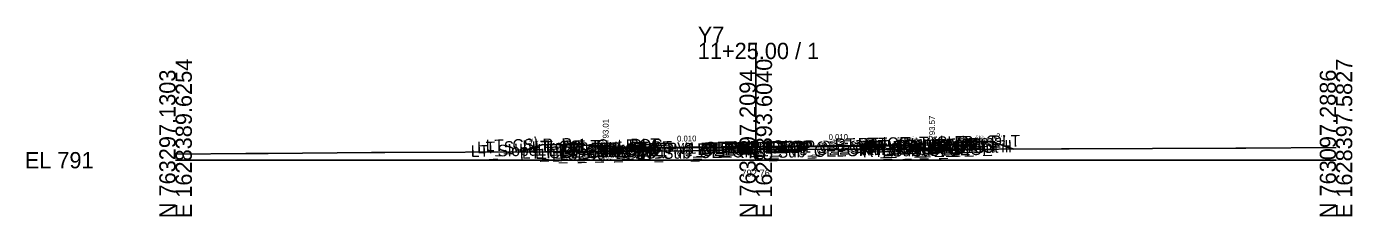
# Model space of a CAD drawing. Extents: x -26 to 203, y -10 to 3017.
# Drawn here: x -25.7 to 202.8, y 2490.3 to 2523 of the extents above; entities that cross this region are included whole.
import ezdxf

# ---------------------------------------------------------------- set-up
doc = ezdxf.new("R2010")
doc.units = 0
for name, color, linetype in [('Default', 7, 'Continuous'), ('Exist Cross Section Cell', 7, 'Continuous'), ('Exist XS Center Line Elevation Label', 7, 'Continuous'), ('Exist XS Ground Line', 7, 'Continuous'), ('Prop CMT Conc Surface', 7, 'Continuous'), ('Prop CMT Concrete Structures', 7, 'Continuous'), ('Prop CMT Pvmt Course 1', 7, 'Continuous'), ('Prop CMT Pvmt Course 1 CG', 7, 'Continuous'), ('Prop CMT Pvmt Course 2', 7, 'Continuous'), ('Prop CMT Pvmt Course 3', 7, 'Continuous'), ('Prop CMT Pvmt Surface', 7, 'Continuous'), ('Prop CMT Slope Grass', 7, 'Continuous'), ('Prop CMT Subgrade Earthwork', 7, 'Continuous'), ('Prop XS Hydro Elevations', 7, 'Continuous'), ('Prop XS SE Text', 7, 'Continuous'), ('Prop XS Side Slope Text', 7, 'Continuous'), ('Scratch_Level_0', 7, 'Continuous')]:
    doc.layers.add(name, color=color, linetype=linetype)

msp = doc.modelspace()

# ---------------------------------------------------------------- linework, layer by layer
at = {"layer": 'Exist Cross Section Cell'}
for p, q in [((100, 2500), (100, 2520.22)), ((0, 2500), (100, 2500)), ((100, 2500), (200, 2500))]:
    msp.add_line(p, q, dxfattribs=at)
at = {"layer": 'Exist XS Ground Line'}
msp.add_lwpolyline([(0, 2501.03), (12.12, 2501.13), (14.45, 2501.15), (15.97, 2501.16), (33.79, 2501.3), (36.07, 2501.31), (63.79, 2501.44), (64.5, 2501.44), (71.82, 2501.47), (76.09, 2501.54), (77.94, 2501.51), (81.73, 2501.57), (88.9, 2501.61), (94.12, 2501.71), (100, 2501.76), (116.44, 2501.9), (118.29, 2501.87), (119.92, 2501.85), (122.36, 2501.84), (126.12, 2501.84), (127.58, 2501.85), (131.01, 2501.84), (152.68, 2501.93), (154, 2501.94), (182.73, 2502.05), (183.61, 2502.06), (184.48, 2502.06), (200, 2502.19)], dxfattribs=at)
at = {"layer": 'Prop CMT Conc Surface'}
for points in [[(74.13, 2502.01), (74.13, 2502.51), (73.63, 2502.51)], [(128.38, 2502.63), (130.38, 2502.57)], [(130.38, 2502.57), (130.38, 2503.07), (130.88, 2503.07)], [(76.13, 2502.11), (74.13, 2502.01)]]:
    msp.add_lwpolyline(points, dxfattribs=at)
at = {"layer": 'Prop CMT Concrete Structures'}
for points in [[(76.13, 2502.11), (74.13, 2502.01), (74.13, 2502.51), (73.63, 2502.51)], [(73.63, 2502.51), (73.63, 2501.5), (76.13, 2501.52)], [(128.38, 2502.63), (130.38, 2502.57), (130.38, 2503.07), (130.88, 2503.07)], [(130.88, 2503.07), (130.88, 2502.07), (128.38, 2502.05)], [(128.38, 2502.05), (128.38, 2502.63)], [(76.13, 2501.52), (76.13, 2502.11)]]:
    msp.add_lwpolyline(points, dxfattribs=at)
at = {"layer": 'Prop CMT Pvmt Course 1'}
for points in [[(100, 2502.35), (128.38, 2502.63)], [(127.38, 2502.5), (100, 2502.22)], [(127.38, 2502.37), (127.38, 2502.5)], [(128.38, 2502.63), (128.38, 2502.38)], [(100, 2502.35), (76.13, 2502.11)], [(76.13, 2502.11), (76.13, 2501.86)], [(76.13, 2501.86), (77.13, 2501.87)], [(77.13, 2501.99), (100, 2502.22)], [(77.13, 2501.87), (77.13, 2501.99)], [(100, 2502.1), (100, 2502.35)], [(100, 2502.1), (100, 2502.35)], [(100, 2502.22), (100, 2502.1), (100, 2502.1)], [(100, 2502.22), (100, 2502.1), (100, 2502.1)], [(128.38, 2502.38), (127.38, 2502.37)]]:
    msp.add_lwpolyline(points, dxfattribs=at)
at = {"layer": 'Prop CMT Pvmt Course 1 CG'}
for points in [[(76.13, 2501.52), (73.13, 2501.49), (72.8, 2501.16)], [(72.8, 2501.16), (76.13, 2501.19)], [(128.38, 2502.05), (131.38, 2502.08), (131.71, 2501.75)], [(131.71, 2501.75), (128.38, 2501.71)]]:
    msp.add_lwpolyline(points, dxfattribs=at)
at = {"layer": 'Prop CMT Pvmt Course 2'}
for points in [[(77.13, 2501.87), (76.13, 2501.86)], [(76.13, 2501.86), (76.13, 2501.52)], [(76.13, 2501.52), (77.13, 2501.53)], [(77.13, 2501.53), (77.13, 2501.87)], [(127.38, 2502.37), (128.38, 2502.38)], [(127.38, 2502.04), (127.38, 2502.37)], [(128.38, 2502.05), (127.38, 2502.04)], [(128.38, 2502.38), (128.38, 2502.05)]]:
    msp.add_lwpolyline(points, dxfattribs=at)
at = {"layer": 'Prop CMT Pvmt Course 3'}
for points in [[(77.13, 2501.53), (76.13, 2501.52)], [(76.13, 2501.19), (77.13, 2501.2)], [(77.13, 2501.2), (77.13, 2501.53)], [(127.38, 2502.04), (128.38, 2502.05)], [(127.38, 2501.7), (127.38, 2502.04)], [(128.38, 2501.71), (127.38, 2501.7)]]:
    msp.add_lwpolyline(points, dxfattribs=at)
at = {"layer": 'Prop CMT Pvmt Surface'}
for points in [[(100, 2502.35), (128.38, 2502.63)], [(100, 2502.35), (76.13, 2502.11)]]:
    msp.add_lwpolyline(points, dxfattribs=at)
at = {"layer": 'Prop CMT Slope Grass'}
for points in [[(73.63, 2502.51), (63.28, 2502.72), (59.38, 2501.42)], [(130.88, 2503.07), (140.38, 2503.26)], [(140.38, 2503.26), (144.48, 2501.89)]]:
    msp.add_lwpolyline(points, dxfattribs=at)
at = {"layer": 'Prop CMT Subgrade Earthwork'}
for p, q in [((77.13, 2501.2), (77.13, 2501.52)), ((127.38, 2501.7), (127.38, 2501.85))]:
    msp.add_line(p, q, dxfattribs=at)
for points in [[(76.13, 2501.19), (72.8, 2501.16), (71.4, 2502.55)], [(128.38, 2501.71), (131.71, 2501.75), (133.08, 2503.11)], [(77.13, 2501.2), (76.13, 2501.19)], [(127.38, 2501.7), (128.38, 2501.71)]]:
    msp.add_lwpolyline(points, dxfattribs=at)

# ---------------------------------------------------------------- texts
at = {"layer": 'Default'}
msp.add_text('-', height=0.0001, dxfattribs=at).set_placement((0, 2500))
at = {"layer": 'Exist Cross Section Cell'}
for s, p in [('Y7', (90, 2520.22)), ('11+25.00 / 1', (90, 2517.42)), ('EL 791', (-26, 2498.6))]:
    msp.add_text(s, height=2.8, dxfattribs=at).set_placement(p)
for s, p in [('E 1628389.6254', (2.8, 2490)), ('E 1628393.6040', (102.8, 2490)), ('E 1628397.5827', (202.8, 2490)), ('N 763297.1303', (0, 2490)), ('N 763197.2094', (100, 2490)), ('N 763097.2886', (200, 2490))]:
    msp.add_text(s, height=2.8, rotation=90, dxfattribs=at).set_placement(p)
at = {"layer": 'Exist XS Center Line Elevation Label'}
msp.add_text('792.76', height=1.2, dxfattribs=at).set_placement((97.51, 2497.16))
at = {"layer": 'Prop XS Hydro Elevations'}
for s, p in [('793.01', (74.63, 2503.01)), ('793.57', (130.88, 2503.57))]:
    msp.add_text(s, height=1, rotation=90, dxfattribs=at).set_placement(p)
at = {"layer": 'Prop XS SE Text'}
for p in [(86.43, 2503.21), (112.55, 2503.47)]:
    msp.add_text('0.010', height=1, rotation=0.5729, dxfattribs=at).set_placement(p)
at = {"layer": 'Prop XS Side Slope Text'}
for rotation, p in [(18.4332, (60.83, 2502.69)), (341.5668, (141.22, 2503.77))]:
    msp.add_text('3:1', height=1, rotation=rotation, dxfattribs=at).set_placement(p)
at = {"layer": 'Scratch_Level_0'}
for s, p in [('LT_Slope_Fill', (50.9, 2500.55)), ('LT_Sub_Trench_Out_DLT', (51.99, 2501.16)), ('LT_CSLP_Pnt', (53.47, 2501.52)), ('LT_CG1_Shelf_Out', (59.71, 2500.23)), ('LT_CG_Top_Face', (61.42, 2501.25)), ('LT_CG_Top_BOC', (61.94, 2501.27)), ('LT_CG_Bot_BOC', (61.97, 2500.27)), ('LT_CG_Top_Gut', (62.39, 2500.77)), ('LT_CG_Bot_IE', (66.07, 2500.32)), ('LT_PV2_OEOT', (66.33, 2500.66)), ('LT_PV3_OEOT', (66.33, 2500.33)), ('LT_PV1_OEOT', (66.9, 2500.92)), ('LT_Sub_OEEOP', (79.44, 2500.12)), ('LT_PV2_OEEOP', (79.53, 2500.79)), ('LT_PV3_OEEOP', (79.53, 2500.45)), ('LT_PV1_OEEOP', (80.1, 2500.92)), ('RT_PV2_IEEOP', (89.93, 2500.9)), ('LT_PV2_IEEOP', (89.97, 2500.9)), ('RT_PV1_IEEOP', (90.49, 2501.03)), ('LT_PV1_IEEOP', (90.54, 2501.03)), ('PV2_PGL', (93.93, 2500.98)), ('PV1_PGL', (94.49, 2501.24)), ('RT_Sub_OEEOP', (98.74, 2500.31)), ('RT_PV2_OEEOP', (98.84, 2500.98)), ('RT_PV3_OEEOP', (98.84, 2500.64)), ('RT_PV1_OEEOP', (99.4, 2501.11)), ('RT_Sub_Trench_Out_DLT', (113.62, 2501.73)), ('RT_CG_Top_Face', (117.62, 2501.82)), ('RT_CG1_Shelf_Out', (117.91, 2500.81)), ('RT_CG_Bot_IE', (118.27, 2500.84)), ('RT_Sub_OEOT', (118.44, 2500.51)), ('RT_PV2_OEOT', (118.53, 2501.18)), ('RT_PV3_OEOT', (118.53, 2500.85)), ('RT_CG_Top_Gut', (118.59, 2501.33)), ('RT_PV1_OEOT', (119.1, 2501.44)), ('RT_CG_Top_BOC', (119.14, 2501.84)), ('RT_CG_Bot_BOC', (119.17, 2500.84)), ('RT_Sub_OEOP', (121.8, 2500.55)), ('RT_CSLP_Pnt', (124.28, 2501.94)), ('RT_Slope_Fill', (127.32, 2501.05)), ('LT_Sub_OEOP', (62.93, 2499.96)), ('LT_Sub_OEOT', (66.23, 2499.99))]:
    msp.add_text(s, height=2, rotation=1.1458, dxfattribs=at).set_placement(p)

doc.saveas('drawing.dxf')
